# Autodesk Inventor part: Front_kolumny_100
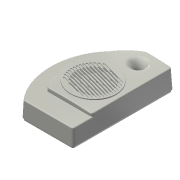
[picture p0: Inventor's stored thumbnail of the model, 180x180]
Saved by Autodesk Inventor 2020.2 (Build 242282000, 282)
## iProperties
Created: 2010-12
Part Number: Front_kolumny_100
Document SubType Name: Modeling
Designer: F.Stasiak
Density: 1 g/cm^3
Material: Ogólny
Appearance: Gładkie — w kolorze kości słoniowej
Manager: www.cadconsulting.pl
Company: Fabian Stasiak CAD Consulting
Author: F.Stasiak
Subject: Zbiór ćwiczeń. Autodesk Inventor 2020. Kurs podstawowy
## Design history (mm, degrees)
sketch "Szkic1"
  geometry: L1 (0, 0)-(0, 200); L2 (0, 200)-(-65, 200); L3 (0, 0)-(-100, 0); A1 r 130 centre (-2.514, 86.002) between (-65, 200) and (-100, 0)
  constraints: 6 end point, 2 point on circle, 1 centre point, 1 parallel, 1 perpendicular, 1 vertical
  dimensions: "d0" = 200 distance of L1.start L1.end; "d1" = 65 distance of L1.end L2.end; "d2" = 100 distance of L1.start L3.end; "d3" = 130 radius of A1
extrude "Wyciągnięcie proste1" new body sketch "Szkic1" distance "d4" = 30; taper "d5" = 0 deg
sketch "Szkic3"
  geometry: L1 (0, 0)-(-100, 0) reference; L2 (0, 200)-(0, 0) reference; L3 (-65, 200)-(0, 200) reference; L4 (0, 38.775)-(-90, 38.775); A1 r 130 centre (-2.514, 86.002) between (-65, 200) and (-100, 0) reference; A2 r 110 centre (0, 102.02) between (-50, 200) and (-90, 38.775); 1 further point
  constraints: 3 point on line, 2 end point, 2 point on circle, 1 centre point, 1 parallel
  dimensions: "d11" = 90 distance of L4.start L4.end; "d12" = 50 distance from line of L2 A2.start; "d13" = 110 radius of A2
extrude "Wyciągnięcie proste2" join sketch "Szkic3" distance "d14" = 8; taper "d15" = 0 deg
feature "Pochylenie ściany1" dims angle "d16" = 2.5 deg
feature "Pochylenie ściany2" dims angle "d17" = 2.5 deg
sketch "Szkic2"
  geometry: A1 r 900 centre (62.935, -861.801) between (144.257, 34.518) and (-4.9, 35.639); 1 further point
  constraints: 2 point on circle, 1 centre point
  dimensions: "d90" = 900 radius of A1
feature "PowWyciągnięciaProstego1" sketch "Szkic2" dims "d6" = 210, "d7" = 0
feature "Wydłuż2" dims "d18" = 10
node "Płaszczyzna konstrukcyjna2"
sketch "Szkic5"
  geometry: L1 (40, 0)-(40, 38); L2 (0, 0)-(65, 0) reference; L3 (52.399, 38)-(109.651, 38) reference; L4 (46, 0)-(46, 20); L5 (52.399, 38)-(1.659, 38) reference; L6 (57.282, 38)-(40, 38); L7 (46, 0)-(40, 0); A1 r 20 centre (66, 20) between (57.282, 38) and (46, 20); 1 further point
  constraints: 8 end point, 4 point on line, 2 point on circle, 1 centre point, 1 collinear, 1 parallel, 1 perpendicular, 1 tangent, 1 vertical
  dimensions: "d26" = 20 radius of A1; "d27" = 12 diameter of L4 L1; "d28" = 20 distance of L4.start L4.end; "d29" = 40 distance from line of L2.start L1
revolve "Obrót1" sketch "Szkic5" stored, may be unused: angle "d30" = 90 deg
feature "Zamień powierzchnię4"
fillet "Zaokrąglenie3" dims "d19" = 5
fillet "Zaokrąglenie4" dims "d20" = 2
feature "Skorupa1" dims "d22" = 3.5, "d32" = 2
fillet "Zaokrąglenie6" dims "d23" = 1
fillet "Zaokrąglenie8" dims "d33" = 10
node "Płaszczyzna konstrukcyjna1"
fillet "Zaokrąglenie9" dims "d86" = 1
feature "Przesunięcie powierzchni1"
sketch "Szkic7"
  geometry: L1 (3.503, 5.002)-(3.503, 194.998) reference; L2 (5.002, 196.497)-(63.706, 196.497) reference; L3 (97.716, 3.503)-(5.002, 3.503) reference; L4 (34.354, 196.497)-(34.354, 188.497); L5 (3.503, 181.497)-(11.503, 181.497); L6 (85.473, 181.497)-(77.473, 181.497); L7 (3.503, 166.497)-(15.503, 166.497); L8 (100.095, 166.497)-(75.095, 166.497); L9 (3.503, 100)-(9.503, 100); L10 (127.031, 108.292)-(119.031, 108.292); L11 (3.503, 136.497)-(11.503, 136.497); L12 (118.495, 136.497)-(110.495, 136.497); L13 (3.503, 23.503)-(18.503, 23.503); L14 (112.492, 23.503)-(92.492, 23.503); L15 (3.503, 63.503)-(11.503, 63.503); L16 (126.993, 63.503)-(118.993, 63.503); L17 (18.503, 3.503)-(18.503, 23.503); L18 (92.492, 23.503)-(92.492, 3.503); A1 r 126.497 centre (2.514, 86.002) between (98.857, 4.031) and (64.439, 196.305) reference; 1 further point
  constraints: 30 end point, 10 collinear, 7 point on line, 6 parallel, 6 point on circle, 4 perpendicular, 2 midpoint
  dimensions: "d95" = 8 distance of L4.start L4.end; "d96" = 8 distance of L5.start L5.end; "d97" = 8 distance of L6.start L6.end; "d98" = 12 distance of L7.start L7.end; "d99" = 15 distance between parallel lines of L5 L2; "d100" = 30 distance between parallel lines of L7 L2; "d101" = 25 distance of L8.start L8.end; "d102" = 6 distance of L9.start L9.end; "d103" = 8 distance of L10.start L10.end; "d104" = 8 distance of L11.start L11.end; "d105" = 8 distance of L12.start L12.end; "d106" = 60 distance between parallel lines of L11 L2; "d107" = 15 distance of L13.start L13.end; "d108" = 20 distance of L14.start L14.end; "d109" = 20 distance between parallel lines of L13 L3; "d110" = 8 distance of L15.start L15.end; "d111" = 8 distance of L16.start L16.end; "d112" = 60 distance between parallel lines of L3 L15
feature "Żebro1" sketch "Szkic7" dims "d115" = 1, "d116" = 1, "d117" = 0.5 deg
fillet "Zaokrąglenie10" dims "d118" = 2
sketch "SZKIC KRATKI"
  geometry: L1 (0, 4.995)-(0, 195.005) reference; L2 (-97.719, 0)-(-4.995, 0) reference; L3 (-96.052, 106)-(-13.948, 84); L4 (-60.5, 74.474)-(-49.5, 115.526); L5 (-94.758, 110.829)-(-12.654, 88.83); L6 (-93.464, 115.659)-(-11.36, 93.659); L7 (-92.17, 120.489)-(-10.066, 98.489); L8 (-90.875, 125.318)-(-8.772, 103.319); L9 (-89.581, 130.148)-(-7.478, 108.148); L10 (-88.287, 134.978)-(-6.184, 112.978); L11 (-97.346, 101.17)-(-15.242, 79.171); L12 (-96.052, 106)-(-13.948, 84); L13 (-94.758, 110.829)-(-12.654, 88.83); L14 (-93.464, 115.659)-(-11.36, 93.659); L15 (-92.17, 120.489)-(-10.066, 98.489); L16 (-90.875, 125.318)-(-8.772, 103.319); L17 (-89.581, 130.148)-(-7.478, 108.148); L18 (-98.64, 96.341)-(-16.536, 74.341); L19 (-97.346, 101.17)-(-15.242, 79.171); L20 (-96.052, 106)-(-13.948, 84); L21 (-94.758, 110.829)-(-12.654, 88.83); L22 (-93.464, 115.659)-(-11.36, 93.659); L23 (-92.17, 120.489)-(-10.066, 98.489); L24 (-90.875, 125.318)-(-8.772, 103.319); L25 (-99.934, 91.511)-(-17.83, 69.511); L26 (-98.64, 96.341)-(-16.536, 74.341); L27 (-97.346, 101.17)-(-15.242, 79.171); L28 (-96.052, 106)-(-13.948, 84); L29 (-94.758, 110.829)-(-12.654, 88.83); L30 (-93.464, 115.659)-(-11.36, 93.659); L31 (-92.17, 120.489)-(-10.066, 98.489); L32 (-101.228, 86.681)-(-19.125, 64.682); L33 (-99.934, 91.511)-(-17.83, 69.511); L34 (-98.64, 96.341)-(-16.536, 74.341); L35 (-97.346, 101.17)-(-15.242, 79.171); L36 (-96.052, 106)-(-13.948, 84); L37 (-94.758, 110.829)-(-12.654, 88.83); L38 (-93.464, 115.659)-(-11.36, 93.659); L39 (-102.522, 81.852)-(-20.419, 59.852); L40 (-101.228, 86.681)-(-19.125, 64.682); L41 (-99.934, 91.511)-(-17.83, 69.511); L42 (-98.64, 96.341)-(-16.536, 74.341); L43 (-97.346, 101.17)-(-15.242, 79.171); L44 (-96.052, 106)-(-13.948, 84); L45 (-94.758, 110.829)-(-12.654, 88.83); L46 (-103.816, 77.022)-(-21.713, 55.022); L47 (-102.522, 81.852)-(-20.419, 59.852); L48 (-101.228, 86.681)-(-19.125, 64.682); L49 (-99.934, 91.511)-(-17.83, 69.511); L50 (-98.64, 96.341)-(-16.536, 74.341); L51 (-97.346, 101.17)-(-15.242, 79.171); L52 (-96.052, 106)-(-13.948, 84); L53 (-86.993, 139.807)-(-4.889, 117.808); L54 (-88.287, 134.978)-(-6.184, 112.978); L55 (-89.581, 130.148)-(-7.478, 108.148); L56 (-90.875, 125.318)-(-8.772, 103.319); L57 (-92.17, 120.489)-(-10.066, 98.489); L58 (-93.464, 115.659)-(-11.36, 93.659); L59 (-94.758, 110.829)-(-12.654, 88.83); L60 (-105.111, 72.192)-(-23.007, 50.193); L61 (-103.816, 77.022)-(-21.713, 55.022); L62 (-102.522, 81.852)-(-20.419, 59.852); L63 (-101.228, 86.681)-(-19.125, 64.682); L64 (-99.934, 91.511)-(-17.83, 69.511)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; C1 r 40 at (-55, 95); A1 r 42.5 centre (-55, 95) between (-96.052, 106) and (-13.948, 84); 65 further points
  constraints: 130 end point, 2 centre point, 2 midpoint, 2 point on circle, 1 coincident, 1 concentric, 1 perpendicular, 254 other
  dimensions: "d34" = 85 diameter of A1; "d35" = 55 distance from line of L1 A1.centre; "d36" = 95 distance from line of L2 A1.centre; "d37" = 15 deg angle of L3 L2; "d38" = 42.5 distance of L4.start L4.end (= 0.5 x d34); "d41" = 5 distance of L3.start L5.start; "d44" = 5 distance of L3.start L11.start; "d77" = 80 diameter of C1
node "Płaszczyzna konstrukcyjna4"
node "Płaszczyzna konstrukcyjna5"
sketch "SZKIC MONTAŻU GŁOŚNIKA"
  geometry: L1 (-21.459, 128.541)-(-88.541, 128.541); L2 (-88.541, 128.541)-(-88.541, 61.459); L3 (-88.541, 61.459)-(-21.459, 61.459); L4 (-21.459, 61.459)-(-21.459, 128.541); C1 r 42.5 at (-55, 95) reference; A1 r 47.435 centre (-55, 95) between (-21.459, 128.541) and (-88.541, 128.541); 4 further points
  constraints: 8 end point, 5 coincident, 3 point on circle, 2 parallel, 2 perpendicular, 1 centre point, 1 horizontal
sketch "SZKIC KOMINKÓW MONTAŻOWYCH"
  geometry: L1 (75.095, 166.997)-(75.095, 165.997) reference; L2 (15.503, 165.997)-(15.503, 166.997) reference; L3 (3.503, 23.003)-(18.003, 23.003) reference; L4 (19.003, 3.503)-(19.003, 24.003) reference; L5 (18.003, 23.003)-(19.003, 24.003); L6 (92.992, 23.003)-(112.207, 23.003) reference; L7 (91.992, 24.003)-(91.992, 3.503) reference; L8 (92.992, 23.003)-(91.992, 24.003); 5 further points
  constraints: 4 end point, 4 midpoint, 1 perpendicular, 1 point on line
feature "Kratka3" dims "d190" = 5.5, "d191" = 2, "d192" = 3, "d193" = 4, "d194" = 0, "d195" = 2, "d196" = 2, "d197" = 0, "d198" = 10, "d199" = 0, "d200" = 1.5 deg, "d201" = 0, "d202" = 231.89703
feature "Pogrubienie5" dims "d203" = 2, "d204" = 2
feature "Pogrubienie6" dims "d205" = 2, "d206" = 2
feature "Kominek3" dims "d207" = 0, "d208" = 6.6, "d209" = 2.8, "d210" = 6, "d211" = 2 deg, "d212" = 1 deg, "d215" = 2, "d216" = 2, "d217" = 10, "d218" = 0, "d219" = 10 deg, "d220" = 2.5 deg, "d221" = 0, "d222" = 0, "d223" = 0, "d261" = 0, "d262" = 360 deg
feature "Kominek4" dims "d224" = 0, "d225" = 5, "d226" = 2.5, "d227" = 15, "d228" = 2 deg, "d229" = 1 deg, "d232" = 1, "d233" = 20, "d234" = 5, "d235" = 0, "d236" = 2 deg, "d237" = 0, "d238" = 0, "d239" = 0, "d240" = 0, "d263" = 0, "d264" = 360 deg
feature "Występ2" dims "d241" = 4, "d242" = 1.9, "d243" = 0, "d244" = 0, "d245" = 2.5 deg, "d246" = 0.25
feature "Reguła zaokrąglania17" dims "d255" = 1
feature "Reguła zaokrąglania18" dims "d256" = 0.75
feature "Reguła zaokrąglania21" dims "d260" = 0.5
node "Bryła1"
body "Srf1"
node "Pętla rzutowana1"
other parameters: "d24" = 45, "d119" = 12, "d188" = 2
